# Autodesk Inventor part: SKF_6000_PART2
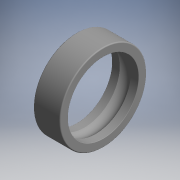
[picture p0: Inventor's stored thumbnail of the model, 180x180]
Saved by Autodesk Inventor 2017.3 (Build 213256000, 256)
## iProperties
Part Number: SKF_6000_PART2
Material: Generic
Catalog Web Link: www.cadenas.de
Description: -Deep groove ball bearings
Vendor: SKF
Document SubType Name: Modeling
Designer: partserver
Manufacturer: SKF
Mass: 19 g
Surface Area: 15.4968 cm^2
Volume: 1.31328 cm^3
Density: 1 g/cm^3
Appearance: PSOLRGB-175-175-175
Category: PARTsolutions
Company: SKF
Title: SKF_6000_PART2
Author: Cadenas PARTsolutions
Comments: Deep groove ball bearings
PSOL_IDENT_0: {$CADENAS_DATA\23d-libs\skf\bearings_units_and_housings\ball_bearings\deep_groove_ball_bearings\bb1_
PSOL_IDENT_1: 001_101.prj},194 {VTYP=3D},{NB=SKF_6000_PART2},{LINA=SKF_6000_PART2},{NN=BB1_001_101_PART2},{NOPRJ=T
PSOL_IDENT_2: RUE},{DATE=18.06.2021 07:30:58},{GEOMDATE=16.06.2021 12:48:44},{VERSION=},{LINEID=5840},{WBVAR=},{WB
PSOL_IDENT_3: NUMERIC=}  {NB=SKF_6000_PART2},{LINA=SKF_6000_PART2},{KT=DUMMY},{DESIGNATION=6000},{R12=0.30},{DD=10
PSOL_IDENT_4: .000},{D=26.000},{B=8.000},{C=},{CX=},{CXX=},{CA=0.000},{XXVARIANT=},{XXDESIGN=Single row},{XXSEALIN
PSOL_IDENT_5: G=No seals},{DESIGN=dgbb1},{DESIGNIR=dgbb1},{VARIANT=},{DD1=14.80},{DD2=},{DD2X=},{DD2A=0.00},{D1=21
PSOL_IDENT_6: .20},{D1X=MIN},{D2=22.6},{D2A=22.60},{D3=},{D3X=},{D3A=0.000},{D4=},{HH=MIN},{BB=MIN},{BBX=},{BBA=0.
PSOL_IDENT_7: 000},{FF=},{R0MAX=MIN},{R0=MIN},{PITCH=17.80},{DW=4.762},{DDAMIN=12.000},{DDAMAX=MIN},{DDBMIN=MIN},{
PSOL_IDENT_8: DDBMAX=MIN},{DBMIN=MIN},{DAMAX=24.000},{BBAMIN=MIN},{CAMAX=MIN},{RAMAX=0.300},{LOAD1=4.750},{LOAD2=1
PSOL_IDENT_9: .960},{LOAD3=0.083},{SPEED1=67000},{SPEED2=40000},{KR=0.025},{F0=12.000},{Z=7},{II=1},{MASS=0.019},{
PSOL_IDENT_10: BEARING=6000},{RING=},{HELP=2.400},{HELP2=1.700},{DD1ALG=7.400},{YALG=7.400},{PITCH1=17.800},{DW1=4.
PSOL_IDENT_11: 762},{YALG1=10.600},{HALG1=2.400},{SH=7.400},{CU=0.648},{HALG=2.4},{B1=0},{SHIELDHELP=1},{D4A=0.000}
PSOL_IDENT_12: ,{FFA=0.000},{RS1=}
NB: SKF_6000_PART2
NT: Deep groove ball bearings
NBSYN: SKF_$DESIGNATION._PART2
LINA: SKF_6000_PART2
CATALOG: SKF
DESIGNATION: 6000
R12: 0.3
DD: 10
D: 26
B: 8
D2: 22.6
LOAD1: 4.75
LOAD2: 1.96
LOAD3: 0.083
SPEED1: 67000
SPEED2: 40000
BEARING: 6000
SUPPLIER: SKF
ARTICLENO: SKF_6000_PART2
BOMINFO: SKF_6000_PART2
CREATOR: CADENAS GmbH
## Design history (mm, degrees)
sketch "Sketch_1"
  geometry: L1 (50, 0)-(-50, 0); L2 (0, 12.7)-(0, 10.7); L3 (0.1, 10.6)-(2.333, 10.6); L4 (5.667, 10.6)-(7.9, 10.6); L5 (8, 10.7)-(8, 12.7); L6 (7.7, 13)-(0.3, 13); A1 r 0.1 centre (0.1, 10.7) between (0, 10.7) and (0.1, 10.6); A2 r 2.381 centre (4, 8.9) between (5.667, 10.6) and (2.333, 10.6); A3 r 0.1 centre (7.9, 10.7) between (7.9, 10.6) and (8, 10.7); A4 r 0.3 centre (7.7, 12.7) between (8, 12.7) and (7.7, 13); A5 r 0.3 centre (0.3, 12.7) between (0.3, 13) and (0, 12.7)
  constraints: 12 end point, 10 point on circle, 5 centre point
revolve "Revolution1" sketch "Sketch_1" stored, may be unused: angle "d0" = 360 deg
body "Solid1"
